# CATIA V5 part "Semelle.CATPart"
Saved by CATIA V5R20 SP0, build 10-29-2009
Part number: Semelle
Bounding box of the stored display mesh (mm): x -13 to 41, y 0 to 37.5, z -28.75 to 6.75
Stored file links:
  E:\Boulot\SeaTech\2eme ANNEE\FabricationAdditive\TP_MOSM_CREM\Projet Sauterelle de serrage\CAO Assemblage Sauterelle\Semelle.CATPart
  E:\Boulot\SeaTech\2eme ANNEE\FabricationAdditive\TP_MOSM_CREM\Projet Sauterelle de serrage\CAO Assemblage Sauterelle\Sauterelle_horizontale_05120-06.CATPart
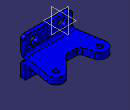
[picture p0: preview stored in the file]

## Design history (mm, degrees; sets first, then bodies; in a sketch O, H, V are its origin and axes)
Body1 (main body)
  Solid1 "05120-06_1": solid without history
